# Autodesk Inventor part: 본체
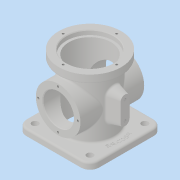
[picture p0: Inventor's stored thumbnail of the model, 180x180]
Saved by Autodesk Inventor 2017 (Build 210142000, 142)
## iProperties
Part Number: 본체
Material: 일반
Document SubType Name: Modeling
Designer: user
Density: 1 g/cm^3
Appearance: 기본값
Author: user
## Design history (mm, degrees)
sketch "스케치1"
  geometry: L1 (57, 57)-(-57, 57); L2 (-57, 57)-(-57, -57); L3 (-57, -57)-(57, -57); L4 (57, -57)-(57, 57); L5 (57, 57)-(-57, -57); L6 (-57, 57)-(57, -57); 1 further point
  constraints: 12 end point, 2 midpoint, 2 parallel, 1 horizontal, 1 perpendicular
  dimensions: "d0" = 114 distance of L3.end L1.start; "d1" = 114 distance of L2.end L3.end
extrude "돌출1" new body sketch "스케치1" distance "d2" = 10; taper "d3" = 0 deg
sketch "스케치2"
  geometry: C1 r 38 at (0, 0); 1 further point
  constraints: 1 centre point, 1 coincident
  dimensions: "d4" = 76 diameter of C1
extrude "돌출2" join sketch "스케치2" distance "d5" = 101; taper "d6" = 0 deg
sketch "스케치3"
  geometry: C1 r 38 at (0, 0) reference; C2 r 49 at (0, 0)
  constraints: 1 centre point, 1 coincident
  dimensions: "d7" = 98 diameter of C2
extrude "돌출3" join sketch "스케치3" distance "d8" = 13; taper "d9" = 0 deg
node "작업 평면1"
sketch "스케치4"
  geometry: L1 (-57, 0)-(57, 0) reference; C1 r 35 at (0, 54); 2 further points
  constraints: 1 centre point, 1 midpoint, 1 vertical alignment
  dimensions: "d29" = 70 diameter of C1; "d30" = 54 distance from line of L1 C1.centre
extrude "돌출4" join sketch "스케치4" distance "d31" = 100; taper "d32" = 0 deg
hole "구멍3" diameter "d35" = 74; stored, may be unused: countersink angle "d39" = 90 deg, drill point angle "d41" = 0 deg; dims "d36" = 6, "d37" = 4, "d38" = 2, "d40" = 7, "d136" = 10, "d137" = 10
hole "구멍4" diameter "d44" = 66; stored, may be unused: countersink angle "d48" = 90 deg, drill point angle "d50" = 118 deg; dims "d42" = 10, "d43" = 10, "d45" = 6, "d46" = 4, "d47" = 2, "d49" = 7
hole "구멍5" diameter "d53" = 48; stored, may be unused: countersink angle "d57" = 90 deg, drill point angle "d59" = 118 deg; dims "d51" = 10, "d52" = 10, "d54" = 6, "d55" = 4, "d56" = 2, "d58" = 7
node "작업 평면2"
sketch "스케치5"
  geometry: L1 (77, 0)-(34, 0); L2 (70, 7)-(41, 7); L3 (41, -7)-(70, -7); L4 (0, 57)-(0, -57) reference; L5 (19, -50)-(89, -50) reference; L6 (0, 0)-(54, 0); A1 r 7 centre (70, 0) between (70, -7) and (70, 7); A2 r 7 centre (41, 0) between (41, 7) and (41, -7); 1 further point
  constraints: 10 end point, 6 point on circle, 4 tangent, 2 centre point, 2 horizontal, 2 point on line, 1 horizontal alignment, 1 midpoint, 1 parallel
  dimensions: "d61" = 7 radius of A1; "d64" = 54 distance of L6.start L6.end; "d68" = 43 distance of L1.end L1.start; "d138" = 20 distance of L1.end L6.end
extrude "돌출5" join sketch "스케치5" stored distance "d70" = 100; taper "d71" = 0 deg
feature "면 기울기1" dims angle "d72" = 15 deg
sketch "스케치7"
  geometry: C1 r 37 at (0, 0) reference; 1 further point
  constraints: 1 vertical alignment
  dimensions: "d73" = 42 distance of C1.centre point (0, -42)
hole "구멍6" sketch "스케치7" at (0, -42) diameter "d74" = 3.242; stored, may be unused: countersink angle "d78" = 90 deg, drill point angle "d80" = 118 deg; dims "d75" = 6, "d76" = 4, "d77" = 2, "d79" = 8
sketch "스케치8"
  geometry: C1 r 24 at (0, 0) reference; 2 further points
  constraints: 1 vertical alignment
  dimensions: "d84" = 31 distance of C1.centre point (0, 31)
hole "구멍7" sketch "스케치8" at (0, 31) diameter "d85" = 3.242; stored, may be unused: countersink angle "d89" = 90 deg, drill point angle "d91" = 118 deg; dims "d86" = 6, "d87" = 4, "d88" = 2, "d90" = 8
hole "구멍8" diameter "d97" = 4.134; stored, may be unused: countersink angle "d101" = 90 deg, drill point angle "d103" = 118 deg; dims "d95" = 10, "d96" = 10, "d98" = 8, "d99" = 4, "d100" = 2, "d102" = 10
hole "구멍9" diameter "d106" = 4.134; stored, may be unused: countersink angle "d110" = 90 deg, drill point angle "d112" = 118 deg; dims "d104" = 10, "d105" = 10, "d107" = 8, "d108" = 4, "d109" = 2, "d111" = 10
fillet "모깎기1" dims "d113" = 14
hole "구멍10" diameter "d116" = 10; stored, may be unused: countersink angle "d120" = 90 deg, drill point angle "d122" = 118 deg; dims "d114" = 10, "d115" = 10, "d117" = 8, "d118" = 4, "d119" = 2, "d121" = 10
fillet "모깎기2" dims "d123" = 3
chamfer "모따기1" distance "d124" = 1; stored, may be unused: second distance "d125" = 2, angle "d126" = 45 deg
chamfer "모따기2" distance "d127" = 1; stored, may be unused: second distance "d128" = 2, angle "d129" = 45 deg
chamfer "모따기3" distance "d130" = 1; stored, may be unused: second distance "d131" = 2, angle "d132" = 45 deg
sketch "스케치9"
  geometry: C1 r 41 at (0, 0) reference; C2 r 50 at (0, 0)
  constraints: 1 centre point, 1 coincident, 1 other
  dimensions: "d133" = 100 diameter of C2
feature "엠보싱1" sketch "스케치9" dims "d0" = 114, "d1" = 114, "d134" = 0.5, "d135" = 0
node "솔리드1"
pattern_circular "원형 패턴1" dims angle "d82" = 360 deg
pattern_circular "원형 패턴2" dims angle "d93" = 360 deg
mirror "미러1"
mirror "미러2"
mirror "미러3"
other parameters: "d60" = 55
